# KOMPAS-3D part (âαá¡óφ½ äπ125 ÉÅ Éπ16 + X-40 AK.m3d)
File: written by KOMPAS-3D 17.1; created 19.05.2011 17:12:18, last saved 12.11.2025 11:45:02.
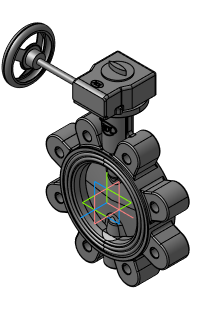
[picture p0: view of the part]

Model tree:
1. Плоскость XY
2. Плоскость ZX
3. Плоскость ZY
4. Ось X
5. Ось Y
6. Ось Z
7. Начало координат
8. Операция без истории:5

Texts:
  Viktor2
